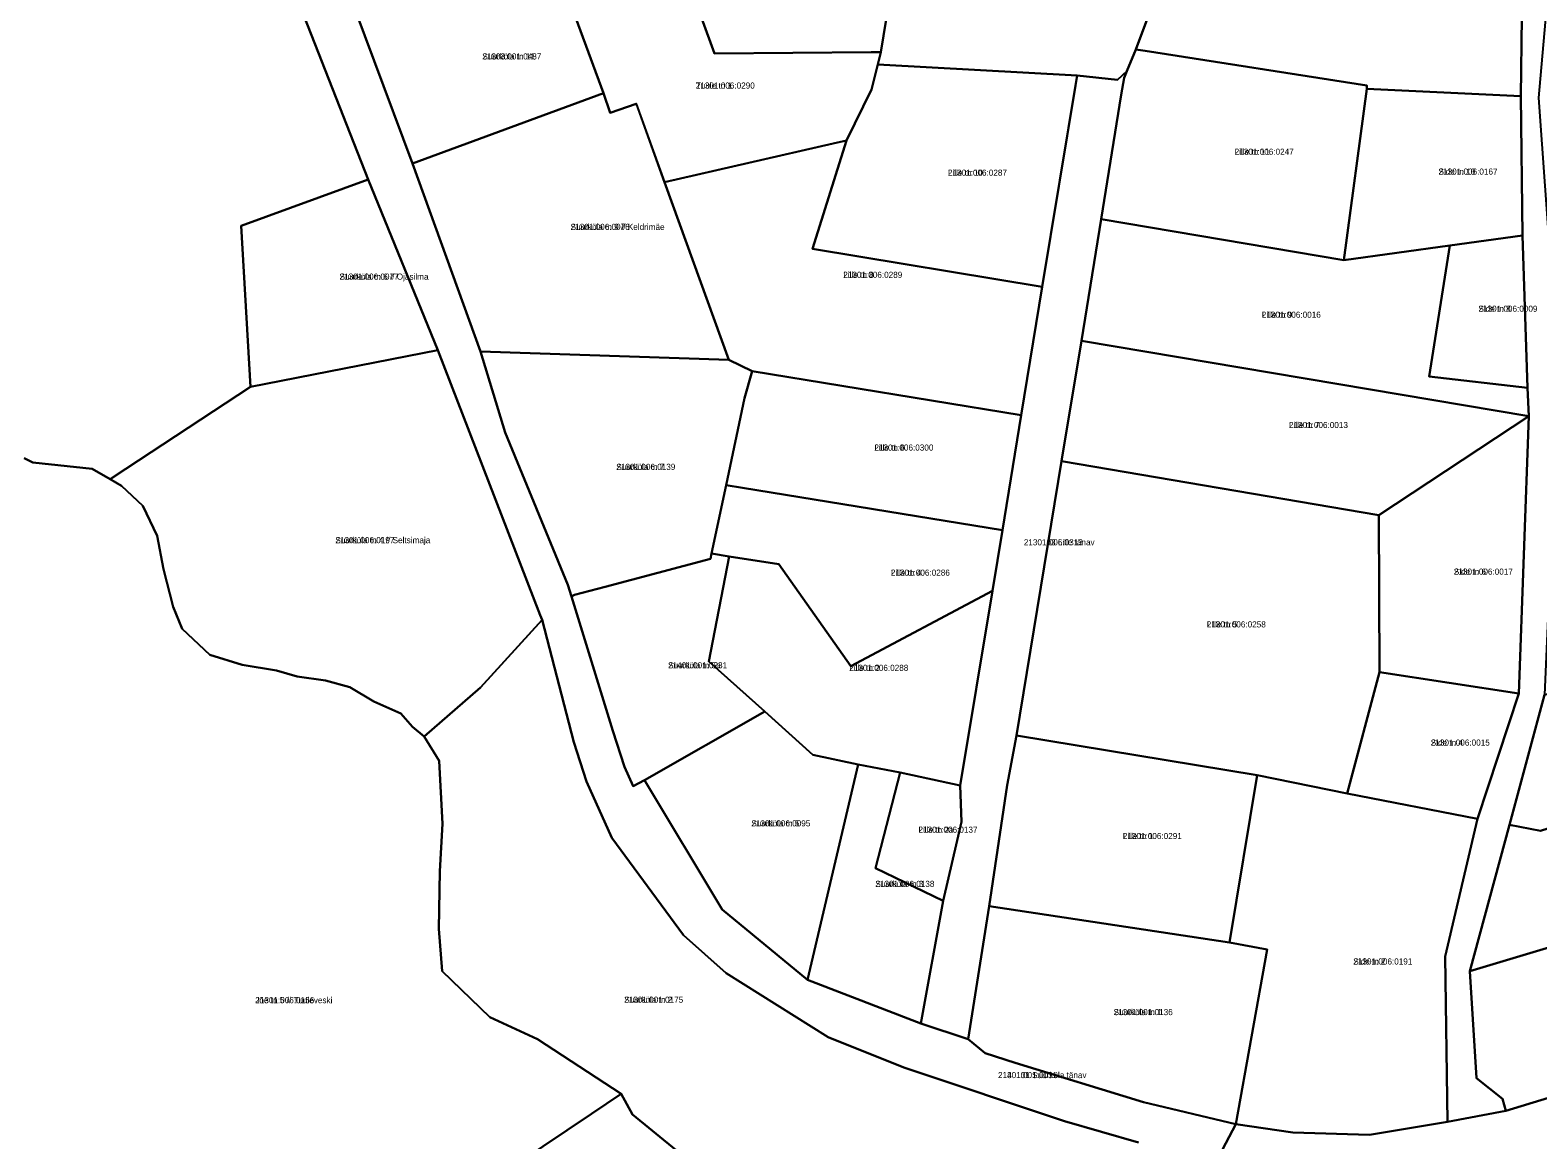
# Model space of a CAD drawing. Extents: x 520985 to 542706, y 6413723 to 6468993.
# Drawn here: x 528814.1 to 529184.5, y 6437658.9 to 6437931.4 of the extents above; entities that cross this region are included whole.
import ezdxf

# ---------------------------------------------------------------- set-up
doc = ezdxf.new("R2010")
doc.units = 0
for name, color, linetype in [('L_AADRESS', 7, 'Continuous'), ('PIIR', 7, 'Continuous'), ('TUNNUS', 7, 'Continuous')]:
    doc.layers.add(name, color=color, linetype=linetype)

msp = doc.modelspace()

# ---------------------------------------------------------------- linework, layer by layer
at = {"layer": 'PIIR'}
for points in [[(528671.84, 6438068.93), (528819.18, 6438074.88), (528855.7, 6438076.3), (528856.82, 6437997.46), (528897.14, 6437894.74), (528865.94, 6437883.4), (528868.23, 6437843.85), (528837.58, 6437823.69), (528833.73, 6437821.16), (528829.29, 6437823.67), (528814.73, 6437825.23), (528812.63, 6437826.3)], [(529086.41, 6437658.27), (529068.18, 6437663.51), (529028.73, 6437676.62), (529010.14, 6437684.08), (528985.11, 6437699.86), (528974.61, 6437709.16), (528957, 6437733.06), (528950.72, 6437746.88), (528947.61, 6437756.58), (528939.83, 6437786.62), (528939.37, 6437787.72), (528914.25, 6437852.88), (528897.14, 6437894.74), (528856.82, 6437997.46)], [(529188.21, 6437955.75), (529184.67, 6437914.83), (529186.99, 6437881.86), (529189.1, 6437836.99), (529187.7, 6437803.92), (529186.1, 6437768.16), (529177.53, 6437736.25), (529167.78, 6437700.3), (529169.4, 6437674.03), (529175.79, 6437668.97), (529176.58, 6437665.99), (529162.25, 6437663.31), (529161.69, 6437703.93), (529169.63, 6437737.7), (529179.82, 6437768.52), (529182.25, 6437836.61), (529181.97, 6437843.59), (529180.72, 6437881.04), (529180.31, 6437915.23), (529180.57, 6437934.75)], [(528889.18, 6437949.23), (528907.97, 6437898.68), (528924.74, 6437852.54), (528930.81, 6437832.61), (528946.21, 6437795.17), (528947.08, 6437792.33), (528957.22, 6437759.37), (528960.07, 6437750.49), (528962.23, 6437745.73), (528964.97, 6437747.25), (528984.09, 6437715.42), (529005.06, 6437698.2), (529032.88, 6437687.42), (529044.53, 6437683.59), (529048.74, 6437680.15), (529056.05, 6437677.78), (529087.56, 6437668.11), (529110.31, 6437662.71), (529094.63, 6437633.04)], [(528812.63, 6437826.3), (528814.73, 6437825.23), (528829.29, 6437823.67), (528833.73, 6437821.16), (528836.54, 6437819.56), (528841.74, 6437814.61), (528845.24, 6437807.23), (528846.87, 6437799.02), (528849.21, 6437789.8), (528851.41, 6437784.43), (528858.23, 6437778.04), (528866.18, 6437775.55), (528874.58, 6437774.18), (528879.68, 6437772.66), (528886.62, 6437771.71), (528892.64, 6437770.03), (528898.48, 6437766.57), (528905.12, 6437763.56), (528907.99, 6437760.34), (528910.87, 6437757.98), (528914.52, 6437751.94), (528915.36, 6437736.5), (528914.74, 6437724.84), (528914.51, 6437710.75), (528915.33, 6437700.29), (528927.02, 6437689.03), (528938.7, 6437683.59), (528959.29, 6437670.18), (528951.97, 6437665.27), (528825.68, 6437580.53)], [(529000.02, 6437634.04), (528962.09, 6437665.1), (528959.29, 6437670.18), (528938.7, 6437683.59), (528927.02, 6437689.03), (528915.33, 6437700.29), (528914.51, 6437710.75), (528914.74, 6437724.84), (528915.36, 6437736.5), (528914.52, 6437751.94), (528910.87, 6437757.98), (528924.74, 6437770.01), (528939.83, 6437786.62), (528947.61, 6437756.58), (528950.72, 6437746.88), (528957, 6437733.06), (528974.61, 6437709.16), (528985.11, 6437699.86), (529010.14, 6437684.08), (529028.73, 6437676.62), (529068.18, 6437663.51), (529086.41, 6437658.27)], [(529022.94, 6437366.13), (529027.17, 6437384.16), (529036.06, 6437422.07), (529055.75, 6437509.24), (529061.56, 6437534.93), (529068.18, 6437561.14), (529077.63, 6437598.5), (529085.06, 6437619.76), (529094.63, 6437633.04), (529110.31, 6437662.71), (529124.29, 6437660.69), (529143.13, 6437660.13), (529162.25, 6437663.31), (529176.58, 6437665.99), (529231.94, 6437682.87)]]:
    msp.add_lwpolyline(points, dxfattribs=at)
for points in [[(529128.89, 6437979.69), (529131.4, 6437979.46), (529169.73, 6437976), (529182.98, 6437970.5), (529184.05, 6437970.06), (529182.24, 6437956.37), (529180.57, 6437934.75), (529180.31, 6437915.23), (529142.45, 6437916.99), (529142.47, 6437917.86), (529087.99, 6437926.37), (529085.7, 6437926.73), (529096.21, 6437954.81), (529096.98, 6437956.64), (529100.1, 6437962.01), (529101.85, 6437963.57), (529124.23, 6437974.09)], [(528954.91, 6437915.94), (528942.45, 6437949.8), (528932.16, 6437977.87), (528972.07, 6437978.03), (528972.28, 6437952.98), (528982.19, 6437925.72), (529020.73, 6437926.02), (529023.07, 6437926.04), (529022.3, 6437923), (529020.76, 6437916.9), (529014.6, 6437904.35), (529011.32, 6437903.6), (528969.9, 6437894.11), (528963.03, 6437913.38), (528962.95, 6437913.35), (528956.57, 6437911.15)], [(528972.28, 6437952.98), (528972.07, 6437978.03), (529030.36, 6437978.28), (529031.58, 6437978.27), (529023.07, 6437926.04), (529020.73, 6437926.02), (528982.19, 6437925.72)], [(529023.07, 6437926.04), (529031.58, 6437978.27), (529093.48, 6437978.22), (529093.77, 6437958.5), (529096.98, 6437956.64), (529096.21, 6437954.81), (529085.7, 6437926.73), (529083.49, 6437921.33), (529081.25, 6437919.25), (529071.31, 6437920.34), (529022.3, 6437923)], [(528889.18, 6437949.23), (528942.45, 6437949.8), (528954.91, 6437915.94), (528907.97, 6437898.68)], [(529087.99, 6437926.37), (529142.47, 6437917.86), (529142.45, 6437916.99), (529136.8, 6437874.94), (529077.17, 6437885), (529082.14, 6437915.57), (529082.82, 6437919.69), (529083.49, 6437921.33), (529085.7, 6437926.73)], [(529014.6, 6437904.35), (529020.76, 6437916.9), (529022.3, 6437923), (529071.31, 6437920.34), (529070.89, 6437917.81), (529062.71, 6437868.37), (529006.25, 6437877.72)], [(529083.49, 6437921.33), (529082.82, 6437919.69), (529082.14, 6437915.57), (529077.17, 6437885), (529072.34, 6437855.1), (529067.46, 6437825.54), (529056.39, 6437758.17), (529054.07, 6437745.98), (529049.67, 6437716.3), (529044.53, 6437683.59), (529032.88, 6437687.42), (529038.4, 6437717.6), (529042.85, 6437736.99), (529042.53, 6437745.93), (529050.49, 6437793.77), (529052.93, 6437808.64), (529057.55, 6437836.85), (529062.71, 6437868.37), (529071.31, 6437920.34), (529081.25, 6437919.25)], [(528907.97, 6437898.68), (528954.91, 6437915.94), (528956.57, 6437911.15), (528962.95, 6437913.35), (528969.9, 6437894.11), (528985.76, 6437850.43), (528924.74, 6437852.54)], [(529180.31, 6437915.23), (529180.72, 6437881.04), (529162.84, 6437878.56), (529136.8, 6437874.94), (529142.45, 6437916.99)], [(528985.76, 6437850.43), (528969.9, 6437894.11), (529011.32, 6437903.6), (529014.6, 6437904.35), (529006.25, 6437877.72), (529062.71, 6437868.37), (529057.55, 6437836.85), (528991.42, 6437847.69)], [(528865.94, 6437883.4), (528897.14, 6437894.74), (528914.25, 6437852.88), (528868.23, 6437843.85)], [(529077.17, 6437885), (529136.8, 6437874.94), (529162.84, 6437878.56), (529157.81, 6437846.4), (529181.97, 6437843.59), (529182.25, 6437836.61), (529072.34, 6437855.1)], [(529162.84, 6437878.56), (529180.72, 6437881.04), (529181.97, 6437843.59), (529157.81, 6437846.4)], [(528914.25, 6437852.88), (528939.37, 6437787.72), (528939.83, 6437786.62), (528924.74, 6437770.01), (528910.87, 6437757.98), (528907.99, 6437760.34), (528905.12, 6437763.56), (528898.48, 6437766.57), (528892.64, 6437770.03), (528886.62, 6437771.71), (528879.68, 6437772.66), (528874.58, 6437774.18), (528866.18, 6437775.55), (528858.23, 6437778.04), (528851.41, 6437784.43), (528849.21, 6437789.8), (528846.87, 6437799.02), (528845.24, 6437807.23), (528841.74, 6437814.61), (528836.54, 6437819.56), (528833.73, 6437821.16), (528837.58, 6437823.69), (528868.23, 6437843.85)], [(529072.34, 6437855.1), (529182.25, 6437836.61), (529145.45, 6437812.32), (529067.46, 6437825.54)], [(528985.76, 6437850.43), (528991.42, 6437847.69), (528989.58, 6437841.05), (528985.06, 6437819.69), (528981.5, 6437802.9), (528981.23, 6437801.57), (528955.35, 6437794.75), (528947.82, 6437792.77), (528947.08, 6437792.33), (528946.21, 6437795.17), (528930.81, 6437832.61), (528924.74, 6437852.54)], [(528985.06, 6437819.69), (528989.58, 6437841.05), (528991.42, 6437847.69), (529057.55, 6437836.85), (529052.93, 6437808.64), (528989.06, 6437819.04)], [(529145.45, 6437812.32), (529182.25, 6437836.61), (529179.82, 6437768.52), (529145.57, 6437773.72)], [(529067.46, 6437825.54), (529145.45, 6437812.32), (529145.57, 6437773.72), (529137.66, 6437743.95), (529115.53, 6437748.42), (529056.39, 6437758.17)], [(528997.99, 6437800.24), (528985.81, 6437802.2), (528981.5, 6437802.9), (528985.06, 6437819.69), (528989.06, 6437819.04), (529052.93, 6437808.64), (529050.49, 6437793.77), (529015.67, 6437775.2)], [(528964.97, 6437747.25), (528962.23, 6437745.73), (528960.07, 6437750.49), (528957.22, 6437759.37), (528947.08, 6437792.33), (528947.82, 6437792.77), (528955.35, 6437794.75), (528981.23, 6437801.57), (528981.5, 6437802.9), (528985.81, 6437802.2), (528980.83, 6437776.41), (528994.55, 6437764.07)], [(529006.38, 6437753.42), (528994.55, 6437764.07), (528980.83, 6437776.41), (528985.81, 6437802.2), (528997.99, 6437800.24), (529015.67, 6437775.2), (529050.49, 6437793.77), (529042.53, 6437745.93), (529027.8, 6437749.09), (529017.52, 6437751.11)], [(529186.1, 6437768.16), (529233.48, 6437783.03), (529232.54, 6437749.9), (529185.11, 6437734.82), (529177.53, 6437736.25)], [(529145.57, 6437773.72), (529179.82, 6437768.52), (529169.63, 6437737.7), (529137.66, 6437743.95)], [(528964.97, 6437747.25), (528994.55, 6437764.07), (529006.38, 6437753.42), (529017.52, 6437751.11), (529005.06, 6437698.2), (528984.09, 6437715.42)], [(529049.67, 6437716.3), (529054.07, 6437745.98), (529056.39, 6437758.17), (529115.53, 6437748.42), (529108.69, 6437707.35)], [(529017.52, 6437751.11), (529027.8, 6437749.09), (529021.78, 6437725.58), (529038.4, 6437717.6), (529032.88, 6437687.42), (529005.06, 6437698.2)], [(529027.8, 6437749.09), (529042.53, 6437745.93), (529042.85, 6437736.99), (529038.4, 6437717.6), (529021.78, 6437725.58)], [(529185.11, 6437734.82), (529232.54, 6437749.9), (529231.1, 6437719.29), (529167.78, 6437700.3), (529177.53, 6437736.25)], [(529169.63, 6437737.7), (529161.69, 6437703.93), (529162.25, 6437663.31), (529143.13, 6437660.13), (529124.29, 6437660.69), (529110.31, 6437662.71), (529117.97, 6437705.63), (529108.69, 6437707.35), (529115.53, 6437748.45), (529137.66, 6437743.95)], [(529175.79, 6437668.97), (529169.4, 6437674.03), (529167.78, 6437700.3), (529231.1, 6437719.29), (529230.5, 6437686.2), (529231.94, 6437682.87), (529176.58, 6437665.99)], [(529044.53, 6437683.59), (529049.67, 6437716.3), (529108.69, 6437707.35), (529117.97, 6437705.63), (529110.31, 6437662.71), (529087.56, 6437668.11), (529056.05, 6437677.78), (529048.74, 6437680.15)], [(528919.5, 6437558.33), (528910.48, 6437560.26), (528825.68, 6437580.53), (528951.97, 6437665.27), (528959.29, 6437670.18), (528962.09, 6437665.1), (529000.02, 6437634.04), (529003.78, 6437628.74), (529004.09, 6437622.7), (529004.35, 6437622.36), (529009.79, 6437616.82), (529010.88, 6437615.69), (529015, 6437611.4), (529016.65, 6437606.54), (529016.66, 6437602.33), (529015.63, 6437596.42), (529012.14, 6437587.86), (528996.85, 6437567.6), (528992.12, 6437560.18), (528989.42, 6437553.36), (528991.06, 6437545.29), (528992.23, 6437543.16), (528974.34, 6437546.88), (528924.06, 6437557.36)]]:
    msp.add_lwpolyline(points, close=True, dxfattribs=at)

# ---------------------------------------------------------------- texts
at = {"layer": 'L_AADRESS'}
for s, p in [('Suurküla tn 11', (528925.16, 6437924.24)), ('Tuule tn 1', (528977.61, 6437917.09)), ('Lille tn 11', (529110.01, 6437900.84)), ('Lille tn 10', (529039.56, 6437895.69)), ('Side tn 10', (529160.08, 6437895.96)), ('Suurküla tn 9 // Keldrimäe', (528946.86, 6437882.38)), ('Suurküla tn 6 // Ojasilma', (528890.09, 6437870.16)), ('Lille tn 8', (529013.84, 6437870.6)), ('Side tn 8', (529169.89, 6437862.27)), ('Lille tn 9', (529116.66, 6437860.8)), ('Lille tn 7', (529123.33, 6437833.71)), ('Lille tn 6', (529021.49, 6437828.17)), ('Suurküla tn 7', (528958.08, 6437823.43)), ('Suurküla tn 4 // Seltsimaja', (528889.07, 6437805.43)), ('2130103 Lille tänav', (529058.19, 6437804.91)), ('Lille tn 4', (529025.53, 6437797.45)), ('Side tn 6', (529163.85, 6437797.7)), ('Lille tn 5', (529103.15, 6437784.74)), ('Suurküla tn 5a', (528970.81, 6437774.7)), ('Lille tn 2', (529015.32, 6437774.07)), ('Side tn 4', (529158.18, 6437755.71)), ('Suurküla tn 5', (528991.25, 6437735.87)), ('Lille tn 2a', (529032.32, 6437734.32)), ('Lille tn 1', (529082.52, 6437732.76)), ('Suurküla tn 3', (529021.73, 6437721.01)), ('Side tn 2', (529139.16, 6437701.95)), ('Jõe tn 5 // Tuuleveski', (528869.38, 6437692.44)), ('Suurküla tn 2', (528960.02, 6437692.56)), ('Suurküla tn 1', (529080.28, 6437689.51)), ('2130101 Suurküla tänav', (529051.86, 6437674.04))]:
    msp.add_text(s, height=1.5, dxfattribs=at).set_placement(p)
at = {"layer": 'TUNNUS'}
for s, p in [('21303:001:0487', (528925.16, 6437924.24)), ('21301:006:0290', (528977.61, 6437917.09)), ('21301:006:0247', (529110.01, 6437900.84)), ('21301:006:0287', (529039.56, 6437895.69)), ('21301:006:0167', (529160.08, 6437895.96)), ('21301:006:0076', (528946.86, 6437882.38)), ('21301:006:0077', (528890.09, 6437870.16)), ('21301:006:0289', (529013.84, 6437870.6)), ('21301:006:0009', (529169.89, 6437862.27)), ('21301:006:0016', (529116.66, 6437860.8)), ('21301:006:0013', (529123.33, 6437833.71)), ('21301:006:0300', (529021.49, 6437828.17)), ('21301:006:0139', (528958.08, 6437823.43)), ('21301:006:0197', (528889.07, 6437805.43)), ('21301:006:0313', (529058.19, 6437804.91)), ('21301:006:0286', (529025.53, 6437797.45)), ('21301:006:0017', (529163.85, 6437797.7)), ('21301:006:0258', (529103.15, 6437784.74)), ('21401:001:0231', (528970.81, 6437774.7)), ('21301:006:0288', (529015.32, 6437774.07)), ('21301:006:0015', (529158.18, 6437755.71)), ('21301:006:0095', (528991.25, 6437735.87)), ('21301:006:0137', (529032.32, 6437734.32)), ('21301:006:0291', (529082.52, 6437732.76)), ('21301:006:0138', (529021.73, 6437721.01)), ('21301:006:0191', (529139.16, 6437701.95)), ('21301:006:0156', (528869.38, 6437692.44)), ('21301:001:0175', (528960.02, 6437692.56)), ('21301:001:0136', (529080.28, 6437689.51)), ('21401:001:0031', (529051.86, 6437674.04))]:
    msp.add_text(s, height=1.5, dxfattribs=at).set_placement(p)

doc.saveas('drawing.dxf')
